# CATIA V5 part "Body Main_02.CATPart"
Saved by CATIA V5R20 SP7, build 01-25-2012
Part number: Body Main_02
Bounding box of the stored display mesh (mm): x 100 to 600, y -300 to 300, z 0 to 610
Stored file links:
  E:\#03 University\#02 영남 이공대\#01 2021\#02 여름 방학\#01 Documents\K-Move Page02 ASD01\Body Main_02.CATPart

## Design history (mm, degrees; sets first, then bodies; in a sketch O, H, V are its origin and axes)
Set1 "Reference Data"
  Point1 "Center Point": (0, 0, 0)
  Plane1 "Plane.1(X Dir=100mm)": type Offset, RefPlane yz-plane, Offset 100
  Plane2 "Plane.2(Plane1 Offset=500mm)": type Offset, RefPlane Plane1, Offset 500
  Extract1: ExtractElem face of Loft1
  Boundary1: Boundary edge of Extract1
Body1 (main body)
  Body2
    Sketch1 on Plane2, origin (600, 0, 0), H (0, 1, 0), V (0, 0, 1)
      arc A1 centre (0, -400) radius 1000 from (105.5556, 594.4134) to (-105.5556, 594.4134) ccw
      point P1 (0, -400)
      point P2 (195, 580.8032)
      point P3 (-195, 580.8032)
      line L1 (-195, 494.9721) -> (-195, 0)
      point P4 (-195, 0)
      line L2 (195, 494.9721) -> (195, 0)
      point P5 (195, 0)
      line L3 (-195, 0) -> (195, 0)
      arc A2 centre (-95, 494.9721) radius 100 from (-105.5556, 594.4134) to (-195, 494.9721) ccw
      arc A3 centre (95, 494.9721) radius 100 from (105.5556, 594.4134) to (195, 494.9721) cw
      radius A1 = 1000
      distance H A1 = 600
      distance L1 L2 = 390
      radius A2 = 100
      radius A3 = 100 {= Sketch1.radius(A2)}
      coincidence: P1 V, P4 H, P5 H, A1 P3, L1 P3, A1 P2, L2 P2
      symmetry: P3 P2 V
      vertical: L1 V, L2 V
      horizontal: L3 H
      tangency: A2 A1, A2 L1, A3 A1, A3 L2
    Sketch2 on Plane1, origin (100, 0, 0), H (0, 1, 0), V (0, 0, 1)
      arc A1 centre (0, -400) radius 1000 from (222.2222, 574.996) to (-222.2222, 574.996) ccw
      point P1 (0, -400)
      point P2 (300, 553.9392)
      point P3 (-300, 553.9392)
      line L1 (-300, 477.4964) -> (-300, 0)
      point P4 (-300, 0)
      line L2 (300, 477.4964) -> (300, 0)
      point P5 (300, 0)
      line L3 (-300, 0) -> (300, 0)
      arc A2 centre (-200, 477.4964) radius 100 from (-222.2222, 574.996) to (-300, 477.4964) ccw
      arc A3 centre (200, 477.4964) radius 100 from (222.2222, 574.996) to (300, 477.4964) cw
      radius A1 = 1000
      distance H A1 = 600
      distance L1 L2 = 600
      radius A2 = 100
      radius A3 = 100 {= Sketch2.radius(A2)}
      coincidence: P1 V, P4 H, P5 H, A1 P3, L1 P3, A1 P2, L2 P2
      symmetry: P3 P2 V
      vertical: L1 V, L2 V
      horizontal: L3 H
      tangency: A2 A1, A2 L1, A3 A1, A3 L2
    Loft1: solid, Sections (Sketch1; Sketch2)
    Fillet1: radius 20, on edge [face of Loft1 | face of Loft1]
    Shell1: ExtOffset 0, Face face of Loft1, IntOffset 5
  Assemble1: tool Body2
  Body3 "Hole Body"
    Sketch3 on yz-plane, origin (0, 0, 0), H (0, 0, 1), V (0, -1, 0)
      circle A1 centre (150, 150) radius 15
      point P1 (150, 150)
      radius A1 = 15
      distance P1 H = 150
      distance P1 V = 150
    Pad1: profile Sketch3, direction (1, 0, 0), up to Plane2
    Mirror1: of the body so far, about zx-plane
  Remove1: tool Body3
  Body4
    Sketch4 on xy-plane, origin (0, 0, 0), H (0, 1, 0), V (-1, 0, 0)
      circle A1 centre (-80, -220) radius 10
      point P1 (-80, -220)
      distance H P1 = 220
      radius A1 = 10
      distance V P1 = 80
    Sketch5 on xy-plane, origin (0, 0, 0), H (0, 1, 0), V (-1, 0, 0)
      circle A1 centre (80, -220) radius 10
      point P1 (80, -220)
      distance H P1 = 220
      radius A1 = 10
      distance V P1 = 80
    Pad2: profile Sketch5, direction (0, 0, 1), length 610
    Pad3: profile Sketch4, direction (0, 0, 1), length 610
  Trim1: tool Body4, faces to keep end face of Pad3; end face of Pad2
